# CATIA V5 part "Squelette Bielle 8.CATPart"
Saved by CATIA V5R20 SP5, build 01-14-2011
Part number: Squelette Bielle 8
Bounding box of the stored display mesh (mm): x -220 to -200, y -250 to 50, z 50 to 110
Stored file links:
  U:\CFAO\Thinkmotion\Squelette Bielle 8.CATPart
  U:\CFAO\Thinkmotion\Bras Articule.CATProduct
  H:\Thinkmotion le vrai\Axe.CATPart
  U:\CFAO\Thinkmotion\Squelette Bielle principale.CATPart
  U:\CFAO\Thinkmotion\Squelette general.CATPart
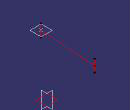
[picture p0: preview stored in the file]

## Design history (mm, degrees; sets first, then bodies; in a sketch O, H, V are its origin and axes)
Set1
  Line1: type PtPt, FirstPoint Point1, SecondPoint Point2
  Line2: type Normal, RefPoint Point2, RefSkin Plane2, Start -30, End 30
  Line3: type Normal, RefPoint Point1, RefSkin Plane2, Start -30, End 30
  Plane1: type OffsetPt, RefPlane xy-plane, RefPoint Point1
Set2
  Point1: linked copy from another document
  Point2: linked copy from another document
  Plane2: linked copy from another document
Body1 (main body)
